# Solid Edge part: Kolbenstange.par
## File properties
Username: ahadarics
Dokumentum tartalom típus: 0
Author: ahadarics
Last saved by: ahadarics
Revision: 81
Sűrűség: 0,000 kg/m^3
Pontosság: 0,990
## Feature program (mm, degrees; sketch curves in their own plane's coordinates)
base feature "unnamed BaseFeature 1"
thread "unnamed Thread 1"
chamfer "Letörés_1" setback 0.5
sketch for "Kihúzás_1" plane through (48, 0, 0) normal (1, 0, 0) x-axis (0, -1, 0)
  circle centre (0, 0) radius 8
extrude "Kihúzás_1" add finite 26.5 along -normal
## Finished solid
Body 1: solid body, 13 faces, 23 edges, 12 vertices.
  Faces by surface: plane 9, cylinder 3, cone 1
  Edges by curve: line 12, circle 11
Bounding box of the edges (mm): 200.000 x 16.000 x 16.000, from (-152, -8, -8) to (48, 8, 8).
Cylindrical faces by radius (mm): R3 x2, R8 x1
Conical faces (half-angle, radius in mm at the cone's reference point): 45 deg R2.5 x1
Planar faces by outward normal: +x 3, +z 1, -x 4, -z 1
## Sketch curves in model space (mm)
circle centre (48, 0, 0) radius 8
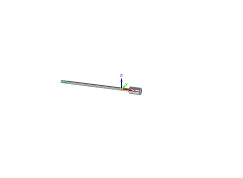
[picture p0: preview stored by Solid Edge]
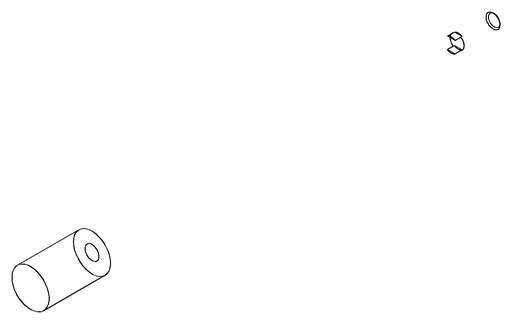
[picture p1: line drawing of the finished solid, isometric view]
